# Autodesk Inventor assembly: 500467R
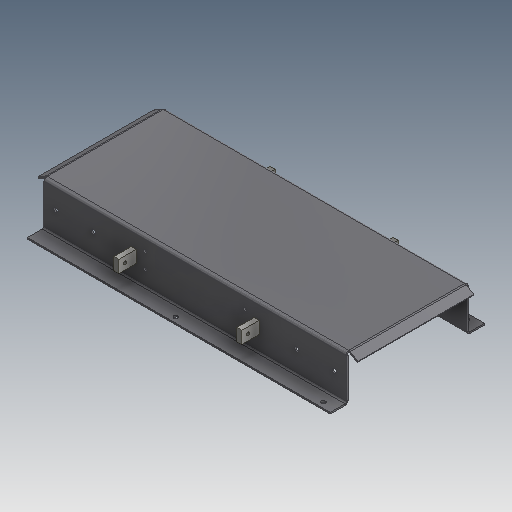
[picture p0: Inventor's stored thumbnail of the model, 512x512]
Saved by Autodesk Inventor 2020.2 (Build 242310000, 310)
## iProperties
Created: 2000-01
Part Number: 500467R
Document SubType Name: Assembly
Designer: cmcgourin
Mass: 1181.22 g
Surface Area: 6327.64 cm^2
Volume: 951.647 cm^3
Density: 1.24123 g/cm^3
Control State: 0
Checked Out: False
Master: False
Shininess: 0.0
Length Units: 11269
Angle Units: 11279
Time Units: 11290
Mass Units: 11283
Length Display Precision: 3
Angle Display Precision: 2
Compacted: True
Dimensions: 650,6x92x317,7 mm
Mass: 1,181 kg
DocNumber: 500467R.iam
Folder: 01 - Themengebiete\Simplification\01 - Packaging machine\
VDS_Category: 3D Komponenten
Density: 0.0
Volumn: 0.0
Area: 0.0
PropertySet Name: Model Information
Author: cmcgourin
Revision Number: -
Title: 500467R
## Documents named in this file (3)
- D:\07 - DEMODATEN\OTX 2019 - Dataset - UPDATE - Dez2019\Designs\07-Packing machine\500467R.iam
- D:\07 - DEMODATEN\OTX 2019 - Dataset - UPDATE - Dez2019\Designs\07-Packing machine\Parts\ADSK-011413.ipt
- D:\07 - DEMODATEN\OTX 2019 - Dataset - UPDATE - Dez2019\Designs\07-Packing machine\Parts\ADSK-011414.ipt
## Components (5 placed, 2 different names)
1. ADSK-011413:1 — Passend:1, Passend:3, Fluchtend:1, Fluchtend:2, Fluchtend:3, Fluchtend:4, Passend:6, Fluchtend:5
2. ADSK-011413:2 — Passend:4, Fluchtend:4, Passend:7
3. ADSK-011413:3 — Passend:2, Fluchtend:3, Passend:6
4. ADSK-011413:4 — Passend:5, Fluchtend:2, Passend:7, Fluchtend:5, Fluchtend:6
5. ADSK-011414:1 — Passend:1, Passend:2, Passend:3, Passend:4, Passend:5, Fluchtend:1
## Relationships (13: Mate 7, Flush 6)
- Passend:1 [Mate]: ADSK-011413:1 ↔ ADSK-011414:1
- Passend:2 [Mate]: ADSK-011413:3 ↔ ADSK-011414:1
- Passend:3 [Mate]: ADSK-011413:1 ↔ ADSK-011414:1
- Passend:4 [Mate]: ADSK-011413:2 ↔ ADSK-011414:1
- Passend:5 [Mate]: ADSK-011413:4 ↔ ADSK-011414:1
- Fluchtend:1 [Flush]: ADSK-011413:1 ↔ ADSK-011414:1
- Fluchtend:2 [Flush]: ADSK-011413:1 ↔ ADSK-011413:4
- Fluchtend:3 [Flush]: ADSK-011413:1 ↔ ADSK-011413:3
- Fluchtend:4 [Flush]: ADSK-011413:1 ↔ ADSK-011413:2
- Passend:6 [Mate]: ADSK-011413:1 ↔ ADSK-011413:3
- Passend:7 [Mate]: ADSK-011413:2 ↔ ADSK-011413:4
- Fluchtend:5 [Flush]: ADSK-011413:1 ↔ ADSK-011413:4
- Fluchtend:6 [Flush]: ADSK-011413:4
